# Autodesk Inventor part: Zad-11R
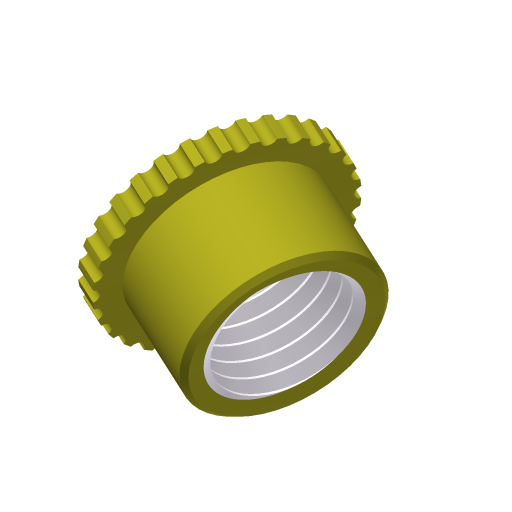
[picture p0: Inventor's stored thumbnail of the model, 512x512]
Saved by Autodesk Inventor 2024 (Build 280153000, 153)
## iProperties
Company: ATC
Created: 2023-03
Part Number: Zad-11R
Document SubType Name: Modeling
Designer: Andrzej Jaskulski
Density: 1 g/cm^3
Material: Ogólny
Appearance: Domyślna
Checked By: A.J.
Engr Approved By: Andrzej Jaskulski
Mfg Approved By: Andrzej Jaskulski
Authority: A.J.
Title: A.J.: Kurs R2024-MEP
Author: Andrzej Jaskulski
Revision Number: 1/24
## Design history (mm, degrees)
derived "Zad-11R-Zespół modelujący.iam"
node "Bryła1"
node "Korpusy bryłowe"
node "Korpusy powierzchniowe"
node "Zad-11R-Surówka.ipt:1" dims "d0" = 10
node "Zad-10R.ipt:1" dims "d0" = 10
